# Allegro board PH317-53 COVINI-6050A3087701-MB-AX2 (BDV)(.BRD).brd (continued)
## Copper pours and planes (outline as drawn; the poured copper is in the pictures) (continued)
VCCPRIM_1P2 on TOP: 250.52,56.24 250.52,54.08 250.69,53.9 251.89,53.9 252.19,54.21 252.19,55.3 252.57,55.68 252.93,55.68 253.13,55.88 253.13,56.54 252.93,56.75 251.02,56.75
VCCSFR on TOP: 229.84,55.43 229.84,54 229.92,53.93 231.82,53.93 231.85,53.95 231.85,56.06 231.8,56.11 230.53,56.11
ACDRV on BOTTOM (solid shape): 45.34,45.77 45.34,44.5 43.3,44.5 43.18,44.63 43.18,45.9 43.3,46.03 45.08,46.03
ACDRV on BOTTOM: 37.59,46.03 38.73,46.03 39.37,46.66 40.13,46.66 40.26,46.79 40.26,48.06 40.13,48.19 39.37,48.19 38.48,47.3 37.59,47.3 37.33,47.04 37.33,46.28
FB_PLLAVDD on L5: 178.9,140.16 178.9,138.78 180.14,137.54 186.88,137.54 193.91,144.58 193.91,156.17 190.22,159.87 189.37,159.87 188.77,159.27 188.77,157.31 190.17,155.91 190.17,144.13 186.31,140.28 179.01,140.28
FB_PLLAVDD on L10: 174.19,121.47 177.63,121.47 178.74,122.59 178.74,139.33 178.45,139.62 178.05,140.02 164.38,140.02 164.15,140.25 164.15,141.6 164.77,142.22 179.23,142.22 179.43,142.42 180.29,142.42 181.16,141.54 181.16,141.18 181.63,140.71 181.63,140.07 181.68,140.01 181.68,139.59 181.81,139.47 181.81,138.74 181.62,138.55 181.62,136.71 181.51,136.61 181.08,136.18 181.08,123.52 181.18,123.42 181.66,123.42 181.78,123.31 181.78,119.56 181.14,118.93 174.24,118.93 174.01,119.15 174.01,121.29
GPPJ_RCOMP on BOTTOM: 258.65,65.11 258.65,64.68 258.9,64.42 259.36,64.42 259.97,65.03 259.97,65.48 259.71,65.74 259.28,65.74
GPU_PLLVDD_XS_SP on L3: 175.27,142.76 180.65,142.76 181.32,142.08 181.32,120.09 179.99,118.76 157.54,118.76 156.92,119.38 156.92,120.57 157.62,121.27 157.62,126.52 155.03,129.11 155.03,129.57 158.75,129.57 158.76,129.55 159.94,129.55 159.95,129.54 159.95,122.64 161.07,121.52 169.04,121.52 169.39,121.18 177.72,121.18 178.2,121.66 178.78,122.24 178.78,139.22 177.67,140.33 174.94,140.33 174.81,140.46 174.81,142.3
GPU_PLLVDD_XS_SP on L5: 175.03,140.47 185.92,140.47 189.84,144.38 189.84,155.88 189.56,156.16 188.14,156.16 185.46,153.49 185.46,148.58 180.26,143.38 175.89,143.38 175.03,142.52
LAN_LX on TOP: 280.69,98.71 280.82,98.84 281.78,98.84 281.78,98.61 281.62,98.45 281.48,98.45 280.62,97.59 280.62,96.24 280.51,96.14 279.63,96.14 279.55,96.22 279.55,98.3 279.63,98.38 280.36,98.38 280.37,98.39 280.39,98.39 280.59,98.49 280.69,98.69
Net_11604 on TOP (solid shape): outline of 162 points within 303.22,181.79 308.51,183.7
Net_11605 on BOTTOM (solid shape): outline of 162 points within 303.22,181.79 308.51,183.7
Net_11606 on TOP (solid shape): outline of 162 points within 2.99,-145.44 8.28,-143.53
Net_11607 on BOTTOM (solid shape): outline of 162 points within 2.99,-145.44 8.28,-143.53
NVHS_DVDD on TOP: 162.08,117.84 161.96,117.97 161.96,118.12 161.89,118.19 161.89,118.76 161.46,119.18 161.46,119.69 161.54,119.76 162.89,119.76 162.89,119.18 163.29,118.77 163.29,117.94 163.2,117.84
NVHS_DVDD on BOTTOM: 161.01,119.06 161.19,118.88 161.45,118.88 161.87,119.3 162.15,119.3 162.24,119.21 162.24,119.01 162.1,118.87 162.1,117.99 162.16,117.94 162.86,117.94 163,118.08 163,118.74 162.87,118.88 162.87,119.13 162.12,119.87 162.12,120.34 161.96,120.5 161.4,120.5 161.01,120.11
NVHS_HVDD on TOP: 164.3,119.18 164.3,120.18 164.82,120.71 164.82,120.76 164.85,120.78 166.33,120.78 166.41,120.7 166.41,120.29 166.41,120.29 166.41,119.53 166.06,119.18
NVHS_HVDD on BOTTOM: 164.95,118.67 164.27,119.35 163.63,119.35 163.25,119.74 163.25,119.87 163.55,120.18 163.55,120.56 163.9,120.91 166.23,120.91 166.44,120.7 166.44,119.74 165.86,119.15 165.86,119.06 165.47,118.67
PUSB3_PWR2 on TOP (solid shape): 309.62,10.14 309.62,6.28 309.09,5.74 307.16,5.74 306.96,5.95 306.96,10.16 307.11,10.32 309.44,10.32
PUSB3_PWR2 on BOTTOM (solid shape): 309.65,11.54 309.65,6.28 309.55,6.18 307.87,6.18 307.77,6.28 307.77,11.56 307.84,11.64 309.55,11.64
PUSB3_PWR2 on L5: 312.75,16.36 313,16.11 313,9.63 309.27,5.9 307.03,5.9 306.83,6.1 306.83,15.85 307.34,16.36
PV_RGLI on TOP: 295.3,80.65 295.3,77.55 292.43,77.55 292.12,77.85 291.46,77.85 291.44,77.83 291.18,77.83 291.18,77.96 291.59,78.36 294.38,78.36 294.51,78.49 294.51,80.65
PV_RGLRO on TOP: 294.13,78.62 291.61,78.62 291.03,78.03 290.8,78.03 290.8,79.23 291.03,79.45 294.13,79.45 294.15,79.43 294.15,78.64
PVADPTR on TOP: 29.59,66.22 30.95,64.86 30.95,63.82 32.18,62.59 32.18,50.85 33.19,49.84 42.97,49.84 43.48,50.35 43.48,53.83 44.62,54.97 44.62,60.2 48.05,63.63 48.05,67.31 40.13,75.24 24.53,75.24 21.94,77.83 21.94,81.69 21.51,82.12 8.38,82.12 7.82,81.56 7.82,70.34 11.93,66.22
PVADPTR on BOTTOM: 13.71,81.84 13.87,81.99 16.18,81.99 16.33,81.84 16.33,78.11 16,77.78 14.14,77.78 13.71,78.21
PVADPTR on BOTTOM: 45.34,54.16 45.72,53.78 45.72,50.22 44.07,48.57 38.6,48.57 38.33,48.84 38.33,49.48 36.4,51.42 36.4,53.74 36.81,54.16
PVCORE on TOP (solid shape): 118.49,129.16 115.67,129.16 115.67,130 115.72,130.05 118.49,130.05
PVCORE on TOP (solid shape): 108.1,130.31 108.1,129.16 106.04,129.16 106.04,130.38 106.24,130.58 107.82,130.58
PVCORE on TOP (solid shape): 114.04,139.37 114.04,138.71 112.06,138.71 112.06,139.53 112.09,139.55 113.86,139.55
PVCORE on TOP (solid shape): 104.26,130.81 104.21,130.76 104.21,128.4 104.04,128.22 103.7,128.22 103.4,128.53 103.4,130.99 104.09,130.99
PVCORE on TOP (solid shape): 110.23,137.14 110.23,135.44 110.21,135.41 109.6,135.41 109.5,135.51 109.5,137.19 109.65,137.34 110.03,137.34
PVCORE on TOP (solid shape): 112.8,136.78 112.8,136.33 112.95,136.17 112.95,135.69 112.16,135.69 112.06,135.79 112.06,136.91 112.67,136.91
PVCORE on TOP (solid shape): 112.85,130.41 112.85,129.21 112.8,129.16 110.92,129.16 110.82,129.26 110.82,129.75 111.66,130.58 112.67,130.58
PVCORE on TOP (solid shape): 106.58,134.75 106.24,134.42 106.24,130.99 105.1,130.99 105.05,131.04 105.05,134.57 105.2,134.73 105.69,134.73 105.69,137.06 106.58,137.06
PVCORE on TOP (solid shape): 109.09,139.5 109.09,139.04 108.84,138.79 104.44,138.79 104.42,138.81 104.42,139.25 104.85,139.68 108.91,139.68
PVCORE on TOP (solid shape): 117.6,136.81 117.6,130.51 117.04,130.51 116.81,130.74 116.81,136.66 117.01,136.86 117.55,136.86
PVCORE on TOP (solid shape): 115.44,136.81 115.44,134.62 115.77,134.29 115.77,133.73 115.97,133.53 116.1,133.53 116.13,133.51 116.13,133.05 115.26,133.05 115.26,133.79 114.5,134.55 114.5,136.88 115.36,136.88
PVCORE on TOP: 113.98,125.37 113.74,125.61 113.74,126.06 113.59,126.2 112.3,126.2 112.25,126.15 112.25,125.91 112.02,125.68 111.33,125.68 111.14,125.68 110.98,125.53 102.15,125.53 101.44,126.24 101.44,126.96 103.1,128.62 103.17,128.55 103.37,128.55 103.4,128.58 103.88,128.58 104.01,128.71 104.01,130.25 103.91,130.36 103.27,130.36 103.18,130.45 103.18,136.34 103.84,137 103.84,137.68 103.88,137.72 103.88,138.87 103.63,139.12 102.36,139.12 102.36,139.14 102.13,139.37 102.13,147.98 100.45,149.66 100.45,156.52 101.22,157.28 101.24,157.28 101.24,158.4 101.39,158.55 102.64,158.55 102.87,158.32 102.87,157.69 103.27,157.28 113.99,157.28 113.99,153.98 113.92,153.9 112.39,153.9 111.91,153.42 111.91,150.17 112.11,149.97 112.44,149.97 112.8,149.61 117.55,149.61 117.83,149.89 117.83,153.67 117.62,153.88 116.66,153.88 116.63,153.9 116.63,158.42 116.66,158.45 117.65,158.45 118.82,157.28 130.07,157.28 130.6,156.75 130.6,145.22 130.43,145.04 119.59,145.04 119.59,144.46 119.08,143.95 119.08,138.04 119.11,138.02 119.11,138.02 119.96,137.17 119.96,127.08 120.34,126.7 120.34,125.5 120.22,125.37 ; 13 cut-outs
PVCORE on BOTTOM: 120.27,136.52 120.21,136.7 120.2,136.72 120.15,136.82 120.13,136.93 119.87,137.2 119.16,137.2 119.07,137.28 119.07,145.49 119.79,144.78 131.64,144.78 131.96,145.1 131.96,151.96 132.64,152.63 132.64,157.61 132.43,157.81 126.15,157.81 126.23,157.89 97.58,157.89 97.57,157.88 96.73,157.88 96.14,157.28 96.14,153.98 96.9,153.98 100.25,150.63 100.25,149.74 101.38,148.61 101.38,147.1 101.94,146.54 101.94,143.65 102.12,143.33 101.94,143.02 101.94,142.35 102.08,142.21 102.12,142.02 102.14,141.98 102.17,141.97 102.29,141.94 102.37,141.86 102.37,141.85 102.49,141.74 102.52,141.74 102.91,141.38 102.52,141.03 102.49,141.03 102.32,140.86 102.26,140.83 102.21,140.81 102.17,140.8 102.15,140.78 102.15,140.77 101.98,140.6 101.98,137.66 102.13,137.51 102.76,137.51 103.13,137.14 119.65,137.14
PVCORE on BOTTOM: 102.05,125.22 101.4,125.88 101.4,128.23 102.39,129.23 119.07,129.23 119.07,127.64 119.45,127.26 120.01,127.26 120.06,127.21 120.65,127.21 120.92,126.94 120.92,126.46 120.93,126.44 121.52,126.44 121.87,126.09 121.87,125.32 121.85,125.3 120.29,125.3 120.29,125.22
PVCORE on L3: 101.27,125.31 101.09,125.49 101.09,134.57 101.98,135.47 101.98,146.28 100.73,147.53 100.73,152.99 101.22,153.47 110.66,153.47 110.66,149.33 111.07,148.92 111.12,148.92 111.35,149.15 118.72,149.15 118.87,149 118.87,138.05 120.34,136.58 120.34,127.08 120.34,127.08 120.33,126.13 119.53,125.33 110.82,125.33 110.8,125.35 110.76,125.31
PVCORE on L5: 113.98,125.37 113.74,125.61 113.74,126.06 113.59,126.2 112.3,126.2 112.25,126.15 112.25,125.91 112.02,125.68 111.33,125.68 111.14,125.68 110.98,125.53 101.09,125.53 100.99,125.63 100.99,153.52 101.22,153.75 111.55,153.75 111.81,153.5 111.81,150.07 112.37,149.51 117.73,149.51 118.01,149.79 118.01,153.62 118.13,153.75 130.37,153.75 130.6,153.52 130.6,145.22 130.43,145.04 119.59,145.04 119.59,144.46 119.08,143.95 119.08,138.04 119.11,138.02 119.11,138.02 119.96,137.17 119.96,127.08 120.34,126.7 120.34,125.5 120.22,125.37 ; 1 cut-out
PVCORE on L6: 101.6,160.2 130.68,160.2 130.68,144.96 119.45,144.96 119.36,140.32 119.36,140.32 119.38,137.29 119.6,137.09 120.27,137.09 120.27,125.53 101.6,125.53 101.6,147.37 101.09,147.88 101.09,159.82 101.34,159.82 101.6,160.07
PVCORE on L8: 101.98,136.55 101.98,146.28 100.73,147.53 100.73,152.53 100.96,152.76 111.15,152.76 111.48,152.43 111.48,150.17 112.14,149.51 117.62,149.51 117.9,149.79 117.9,153.55 118.11,153.75 130.37,153.75 130.65,153.47 130.65,145.27 130.4,145.01 120.28,145.01 120.03,144.76 120.03,137.56 119.02,136.55
PVCORE on L10: 119.99,127.36 114.5,127.36 113.66,126.52 112.52,126.52 112.19,126.85 107.74,126.85 107.72,126.83 103.25,126.83 101.09,128.98 101.09,134.57 101.98,135.47 101.98,146.86 100.96,147.88 100.96,152.78 117.95,152.78 117.95,153.65 126.36,153.65 126.36,153.62 130.04,153.62 130.71,152.96 130.71,145.16 130.4,144.86 128.7,144.86 128.55,145.01 119.78,145.01 119.13,144.36 119.13,137.56 120.16,136.53 120.16,127.54 ; 1 cut-out
PVCORE_DGPU on TOP (solid shape): 204.92,80.01 204.92,78.03 205.27,77.69 207.07,77.69 207.36,77.4 207.36,75.49 207.16,75.29 195.12,75.29 194.94,75.47 194.94,79.58 195.53,80.17 204.77,80.17
PVCORE_DGPU on TOP (solid shape): 184.5,79.05 184.5,75.52 184.27,75.29 169.21,75.29 169.01,75.49 169.01,76.64 169.16,76.79 172.44,76.79 172.62,76.79 175.76,79.94 183.61,79.94
PVCORE_DGPU on TOP: outline of 176 points within 145.28,121.9 177.96,152.43 ; 4 cut-outs
PVCORE_DGPU on BOTTOM: 159.74,71.25 160.45,71.96 162.91,71.96 165.53,74.58 165.53,76.05 166.32,76.84 172.67,76.84 175,79.18 175,79.99 175.13,80.12 184.1,80.12 184.5,79.71 184.5,72.06 184.76,71.81 194.1,71.81 195.02,72.72 195.02,83.09 196.69,84.76 196.69,88.7 196.97,88.98 198.02,88.98 198.12,88.88 198.12,81.36 199.26,80.22 204.72,80.22 205.2,79.73 205.2,78.11 205.46,77.85 207.13,77.85 207.59,77.4 207.59,76.1 208.1,75.59 213.31,75.59 213.81,75.09 213.81,66.15 213.64,65.97 213.64,65.94 159.99,65.94 159.74,66.2
PVCORE_DGPU on BOTTOM: 160.63,143.37 160.63,143.07 160.79,142.91 161.11,142.91 161.22,143.01 161.46,143.01 161.47,143 161.47,142.78 161.6,142.65 161.87,142.65 162.25,142.27 162.25,142.11 162.84,141.52 162.84,141.14 163.57,140.41 178.69,140.41 178.97,140.13 178.97,129.11 178.95,128.99 178.97,128.87 178.97,121.16 178.81,121 159.7,121 159.57,121.13 159.57,122.14 159.25,122.47 159.25,122.56 159.31,122.56 159.31,123.17 159.25,123.17 159.25,128.91 159.31,128.91 159.31,129.7 159.25,129.7 159.25,137.04 156.77,139.52 156.77,140.17 154.79,142.14 154.79,142.33 154.44,142.68 153.51,142.68 153.18,143.01 153.18,143.49 152.57,144.1 151.71,144.1 151.29,144.52 150.73,144.52 149.92,145.33 148.32,145.33 147.47,146.18 147.24,146.18 147.09,146.33 147.09,149.08 146.76,149.41 144.98,149.41 144.88,149.51 144.88,152.71 146.38,154.21 155.98,154.21 156.41,154.64 157.38,154.64 157.76,154.26 157.76,152.1 157.58,151.92 156.97,151.92 156.23,151.18 156.23,148.8 157.34,147.69 157.34,147.09 158.55,145.88 159.41,145.02 159.41,144.52 159.85,144.08 159.85,143.84 160.05,143.64 160.41,143.64 160.52,143.75 160.66,143.75 160.73,143.68 160.73,143.47 ; 22 cut-outs
PVCORE_DGPU on L3: 169.61,121.36 169.31,121.66 161.28,121.66 161.04,121.89 160.97,121.89 160.04,122.83 160.04,136.68 158.88,137.84 153.72,143.01 147.42,143.01 146.45,143.97 146.45,154.11 146.73,154.38 155.72,154.38 156.08,154.03 156.08,148.52 159.26,145.34 160.45,145.34 163.38,142.41 174.23,142.41 174.39,142.25 174.39,140.47 174.81,140.05 177.75,140.05 178.68,139.12 178.68,122.37 177.66,121.36
PVCORE_DGPU on L5: 155.85,72.57 150.36,78.06 150.36,85.91 149.73,86.54 147.01,86.54 145.64,87.91 145.64,95.05 145.39,95.3 145.39,109.38 146.38,110.37 146.38,120.17 145.16,121.39 145.16,125.56 145.51,125.91 145.51,138.99 147.88,141.35 147.88,148.24 153.69,154.05 173.68,154.05 174.44,153.29 174.44,141.07 175.3,140.21 175.71,140.21 175.71,140.2 178.51,140.2 178.65,140.06 178.65,138.8 180.24,137.21 194.31,137.21 195.07,136.45 195.07,99.77 200.4,94.44 200.4,90 208.45,81.94 208.45,72.85 208.2,72.6 206.8,72.6 206.8,72.57 ; 1 cut-out
PVCORE_DGPU on L6: 146.05,137.09 146.05,69.02 153.29,69.02 156.71,65.59 208.4,65.59 208.4,85.02 200.53,85.02 194.94,90.61 194.94,150.22 156.13,150.22 156.13,151.79 151.13,151.79 151.13,142.17 ; 1 cut-out
PVCORE_DGPU on L8: 161.87,141.82 161.35,141.82 158.42,144.76 158.42,145.29 158.13,145.57 157.6,145.57 155.65,147.52 155.65,148.27 155.11,148.82 155.11,149.36 154.38,150.09 154.38,152.28 154.1,152.56 152.02,152.56 149.78,150.32 149.78,147.09 159.85,137.02 159.85,126 160.6,125.25 160.6,121.41 160.7,121.31 177.67,121.31 178.69,122.33 178.69,139.2 177.91,139.98 163.71,139.98 162.54,141.15
PVCORE_DGPU on L10: 169.9,121.54 169.76,121.68 161.18,121.68 160.76,122.11 160.04,122.82 160.04,134.23 159.74,134.53 159.74,137.44 157.91,139.27 157.91,139.32 156.51,140.72 156.51,146.23 156.59,146.31 157.45,146.31 163.78,139.98 163.95,139.81 177.96,139.81 178.64,139.13 178.64,122.88 177.31,121.54
PVPACK on TOP: 17.27,34.22 18.79,34.22 19.05,33.96 19.05,32.06 18.79,31.8 17.4,31.8 17.14,32.06 17.14,34.09
PVPACK on BOTTOM: 17.4,34.73 20.57,34.73 20.82,34.47 20.82,32.16 22.07,30.92 32.76,30.92 33.75,31.91 33.75,32.67 33.91,32.82 38.48,32.82 38.6,32.69 38.6,29.9 38.22,29.52 35.3,29.52 32.36,26.57 17.85,26.57 17.14,27.28 17.14,34.47
PWR_DP on BOTTOM (solid shape): 300.52,38.51 300.52,36.2 300.5,36.18 300.5,36.1 300.27,35.86 297.03,35.86 296.89,36.01 296.89,38.51 297.14,38.76 300.27,38.76
SPK_OUT_L_N on TOP: 24.08,57.18 24.08,57.48 24.69,58.09 25.73,58.09 25.85,57.97 25.85,57.26 25.73,57.13 24.13,57.13
SPK_OUT_L_P on TOP: 24.33,56.06 25.88,56.06 25.88,56.77 25.75,56.9 24.33,56.9 24.13,56.7 24.13,56.26
SPK_OUT_R_L_N on TOP: 26.77,57.2 26.64,57.33 26.64,57.94 26.72,58.02 27.53,58.02 27.84,58.32 28.75,58.32 28.85,58.22 28.85,57.84 28.67,57.66 28.19,57.66 27.73,57.2
SPK_OUT_R_L_P on TOP: 26.72,56.16 28.27,56.16 28.93,56.82 29.33,56.82 29.44,56.92 29.44,57.51 29.38,57.56 28.93,57.56 28.75,57.38 28.27,57.38 27.71,56.82 26.82,56.82 26.72,56.72
SPK_OUT_R_N on TOP: 25.88,58.37 24.74,58.37 24.61,58.25 24.2,58.25 24.19,58.26 24.19,58.54 24.18,58.55 24.18,59.01 24.41,59.24 25.75,59.24 25.9,59.08 25.9,58.4
SPK_OUT_R_P on TOP: 25.9,59.52 24.2,59.52 24.18,59.54 24.18,60.18 24.3,60.3 25.78,60.3 25.9,60.18
SPK_OUT_R_R_N on TOP: 26.62,59.13 26.62,58.4 27.56,58.4 27.75,58.59 28.65,58.59 28.72,58.66 28.72,59.19 28.67,59.24 26.72,59.24
SPK_OUT_R_R_P on TOP: 26.64,60.23 26.64,59.57 26.72,59.49 28.7,59.49 28.8,59.59 28.8,60.3 28.72,60.38 26.79,60.38
UNNAMED_129_BEADSINGLE_I11_INB on BOTTOM: 3.04,80.83 3.04,76.13 3.55,75.62 10.56,75.62 10.84,75.34 10.84,74.17 10.94,74.07 12.44,74.07 12.75,74.37 12.75,76.56 13.01,76.83 13.01,81.21 12.76,81.46 11.81,81.46 11.55,81.21 3.43,81.21
UNNAMED_130_CAPALSP_I76_A on BOTTOM (solid shape): 52.5,33.96 54.33,33.96 54.61,33.68 54.61,30.41 54.45,30.25 52.22,30.25 52.17,30.31 52.17,31.17 51.61,31.73 44.57,31.73 44.47,31.83 44.47,32.77 44.98,33.28 44.98,34.29 45.16,34.47 51.99,34.47
UNNAMED_130_CSC0603_I106_A on BOTTOM: 43.91,33.18 43.81,33.28 40.61,33.28 40.41,33.07 40.41,31.68 39.93,31.19 39.93,29.72 39.6,29.39 39.14,29.39 37.94,28.2 36.62,28.2 36.5,28.07 36.5,25.05 36.65,24.9 43.79,24.9 43.91,25.02
UNNAMED_142_CSC0603_I5_A on BOTTOM (solid shape): 83.44,147.07 83.44,145.8 82.85,145.22 82.39,145.22 81.96,145.65 81.94,145.65 81.23,146.36 81.23,146.66 81.38,146.82 81.38,147.02 81.23,147.17 81.23,147.2 81.66,147.63 81.76,147.63 82.01,147.37 82.37,147.37 82.7,147.7 82.8,147.7
UNNAMED_155_CN102G_I26_1 on BOTTOM (solid shape): 267.13,31.42 267.51,31.42 267.93,31 267.99,30.9 267.99,30.05 266.74,28.8 266.68,28.77 266.61,28.79 266.56,28.83 266.49,28.85 266.1,28.85 265.99,28.81 265.92,28.73 265.91,28.71 261.41,28.71 261.18,28.93 261.18,31.27 261.46,31.55 267,31.55
UNNAMED_160_APCI0020P003A_I103_ on BOTTOM: 64.51,34.65 64.51,52.05 64.84,52.38 64.84,53.6 65.35,54.11 69.21,54.11 69.44,53.88 69.44,52.18 68.04,52.18 66.93,51.06 66.93,39.78 67.28,39.42 69.92,39.42 70.18,39.17 70.18,35.11 69.8,34.73 69.3,34.65
UNNAMED_161_APCI0020P003A_I118_ on BOTTOM: 175.1,23.85 175.23,23.98 182.5,23.98 184.32,25.81 184.32,29.29 176.98,36.63 174.55,36.63 174.42,36.76 174.42,40.87 174.55,41 181.1,41 181.23,40.87 181.23,38.94 181.89,38.28 183.38,38.28 183.51,38.15 183.51,37.77 182.98,37.24 182.98,35.89 187.5,31.37 187.5,23.6 185.9,22 181.02,22 180.9,21.87 180.9,21.97 180.77,21.85 175.23,21.85 175.1,21.97
UNNAMED_166_CN405G_I84_34 on BOTTOM (solid shape): 29.08,64.37 29.36,64.09 29.36,62.77 29.23,62.64 28.62,62.64 28.39,62.87 28.39,64.27 28.55,64.42 29.08,64.42
UNNAMED_166_CN405G_I84_34 on BOTTOM: 27.35,64.7 27.76,65.1 28.14,65.1 28.32,65.28 28.32,66.65 28.42,66.75 28.98,66.75 29.08,66.65 29.08,64.37 29.26,64.19 29.26,62.69 29.16,62.59 27.56,62.59 27.35,62.79
UNNAMED_166_CN405G_I84_39 on TOP: 25.17,65.92 25.17,65.13 25.07,65.03 23.47,65.03 23.36,65.13 23.36,65.89 23.47,65.99 25.09,65.99
UNNAMED_166_CN405G_I84_39 on BOTTOM: 26.54,65.26 26.36,65.08 20.62,65.08 20.37,65.33 20.37,68.61 20.62,68.86 20.62,70.03 22.12,71.53 25.5,71.53 25.47,71.5 25.47,69.24 25.57,69.14 26.41,69.14 26.54,69.02
UNNAMED_166_FUSE_I171_1 on BOTTOM (solid shape): 48.59,85.37 48.59,80.01 48.43,79.86 47.82,79.86 47.55,80.14 47.55,80.34 47.47,80.42 47.36,80.42 47.35,80.43 46.8,80.43 46.8,80.42 46.66,80.42 46.45,80.62 46.45,85.3 46.68,85.53 48.43,85.53
UNNAMED_166_NCT3521U_I118_OUT on BOTTOM: 18.67,79.43 18.67,77.73 18.72,77.68 19.61,77.68 20.11,78.18 20.75,78.18 20.85,78.08 20.85,77.93 21.13,77.65 22.15,77.65 22.35,77.85 22.35,79.58 22.22,79.71 18.95,79.71
UNNAMED_259_CSC0402_I133_A on BOTTOM: 288.85,101.43 290.42,101.43 290.52,101.32 290.52,99.47 290.34,99.29 288.92,99.29 288.72,99.09 288.72,97.46 288.46,97.21 287.65,97.21 287.4,97.46 287.4,97.52 287.43,97.59 287.52,97.61 287.55,97.6 287.85,97.6 287.99,97.67 288.05,97.8 288.05,98.2 288.02,98.29 287.94,98.37 287.9,98.44 287.95,98.52 288.02,98.59 288.05,98.69 288.05,99.08 287.99,99.22 287.85,99.29 287.75,99.29 287.68,99.33 287.67,99.41 287.63,99.67 287.43,99.83 287.4,99.85 287.4,100.27 287.42,100.33 287.48,100.36 287.81,100.71 287.48,101.07 287.42,101.1 287.4,101.16 287.4,101.78 287.44,101.79 287.72,102.07 287.55,102.44 287.51,102.51 287.53,102.58 287.62,102.9 287.4,103.15 287.39,103.16 287.07,103.48 287.07,106.53 287.4,106.86 287.41,106.88 288.05,107.71 288.4,108.69 288.4,108.7 288.79,109.1 290.32,109.1 290.52,108.89 290.52,107.04 290.39,106.91 288.95,106.91 288.74,106.71 288.74,104.64 288.71,104.57 288.64,104.55 288.25,104.19 288.64,103.84 288.71,103.82 288.74,103.75 288.74,101.53
UNNAMED_265_APL3523A_I456_8 on BOTTOM: 227.96,33.48 228.04,33.56 228.04,35.21 227.96,35.28 225.8,35.28 225.8,35.69 225.78,35.72 225.55,35.72 225.37,35.89 224.53,35.89 224.41,35.77 224.41,33.61 224.53,33.48
UNNAMED_265_APL3523A_I456_13 on BOTTOM (solid shape): 232.91,35.28 232.91,34.22 232.64,33.94 232.41,33.94 232.41,33.77 232.4,33.77 232.4,32.74 232.38,32.72 231.7,32.72 230.86,33.56 229.46,33.56 229.37,33.64 229.37,34.02 229.36,34.09 229.33,34.16 229.33,34.93 229.87,35.46 232.74,35.46
UNNAMED_265_APL3523A_I457_13 on BOTTOM (solid shape): 278.43,61.7 278.43,59.57 278.23,59.36 277.49,59.36 276.98,59.87 276.64,59.87 276.64,59.88 275.61,59.88 275.54,59.95 275.54,61.47 275.84,61.78 278.36,61.78
UNNAMED_319_CSC0402_I39_A on BOTTOM (solid shape): 151.66,165.1 151.66,162.77 151.53,162.64 146.66,162.64 146.38,162.92 145.97,162.92 145.97,163.02 145.72,163.27 145.72,163.35 145.56,163.5 145.55,163.52 145.11,163.52 145.11,164.01 145.21,164.11 145.74,164.11 145.87,164.24 145.87,165.23 145.97,165.33 151.43,165.33
UNNAMED_319_CSC0603_I29_A on BOTTOM (solid shape): 154.5,169.67 154.76,169.67 155.07,169.36 155.09,169.3 155.11,169.26 155.11,166.07 154.86,165.81 154.67,165.81 154.67,165.82 154.22,165.82 154.14,165.9 154.02,166.1 154.02,166.35 153.92,166.45 153.41,166.45 153.41,166.7 153.72,167.01 153.72,168.38 153.31,168.79 153.31,169.68 154.48,169.68
UNNAMED_403_APL3537BHAI_I10_A1 on BOTTOM: 159.79,88.83 159.79,88.07 159.89,87.96 160.75,87.96 160.79,88 160.84,88 161.03,88.19 161.03,88.98 160.98,89.03 159.99,89.03
UNNAMED_410_NMOSC_I395_D on BOTTOM (solid shape): 208.02,177.78 208.02,176.23 207.72,175.92 202.76,175.92 201.8,176.89 201.8,177.78 201.88,177.85 207.95,177.85
UNNAMED_410_NMOSC_I397_D on TOP (solid shape): 213.89,171.5 213.89,170.06 213.76,169.93 205.79,169.93 205.74,169.98 205.74,171.58 205.81,171.66 213.74,171.66
UNNAMED_410_NMOSC_I444_D on BOTTOM (solid shape): 201.04,88.9 201.04,84.74 200.94,84.64 200.12,84.64 200.02,84.53 200.02,83.01 199.77,82.76 198.9,82.76 198.8,82.86 198.8,88.75 199.06,89.01 200.94,89.01
USB_CHR_POWER on TOP (solid shape): 300.35,33.18 301.24,33.18 301.24,32.87 301.22,32.85 299.67,32.85 299.62,32.79 297.53,32.79 297.46,32.87 297.46,33.33 297.51,33.38 300.15,33.38
USB_CHR_POWER on TOP: 286.46,32.26 287.42,32.26 287.55,32.13 287.91,32.13 288.49,31.55 294.8,31.55 297.59,31.56 298.07,32.03 298.07,33.38 297.25,33.38 296.52,32.64 295.68,32.64 295.17,32.13 290.75,32.13 290.65,32.24 290.65,32.54 289.96,33.23 288.74,33.23 288.46,32.95 286.46,32.95 286.33,32.82 286.33,32.39
USB_CHR_POWER on TOP: 301.11,25.05 302.66,26.6 305.08,26.6 306.12,27.64 306.12,29.49 305.74,29.87 302.21,29.87 301.69,29.35 301.69,28.01 301.16,27.49 299.79,27.49 297.89,25.58 297.89,21.24 298.14,20.98 300.3,20.98 301.11,21.8
USB_CHR_POWER on BOTTOM: 305.89,28.38 306.22,28.71 306.22,29.72 304.31,31.63 301.6,31.63 301.52,31.55 301.52,28.86 302,28.38
USB_CHR_POWER on L10: 289.56,34.24 302.49,34.24 303.17,33.56 303.17,31.25 303.67,30.75 305.98,30.75 306.19,30.53 306.19,28.68 305.97,28.45 301.65,28.45 299.11,30.99 289.53,30.99 289.28,31.25 289.28,33.96
VADPBL on BOTTOM (solid shape): 44.73,48.19 44.81,48.14 44.82,48.05 44.8,48.01 44.79,47.97 44.79,47.58 44.86,47.44 45,47.37 45.27,47.37 45.34,47.37 45.34,46.54 45.08,46.28 42.8,46.28 42.67,46.16 42.67,44.63 38.22,44.63 37.97,44.89 37.97,45.77 38.99,45.77 39.62,46.41 40.51,46.41 40.76,46.66 40.76,48.06 40.89,48.19
VRA_SY8284_VCC on TOP (solid shape): 199.29,174.68 199.84,174.68 199.89,174.63 199.89,174.27 199.84,174.22 198.4,174.22 198.17,174.45 198.17,174.98 198.24,175.06 198.9,175.06
VRACHG_MP1 on BOTTOM: 39.24,44.25 45.97,44.25 46.22,44.5 46.22,45.01 46.35,45.14 46.86,45.14 46.99,45.01 46.99,40.57 46.61,40.19 45.06,40.19 43.91,39.04 39.37,39.04 38.99,39.42 38.99,44
VRACPU_PH1 on BOTTOM (solid shape): 97.28,169.85 97.28,168.71 97.53,168.46 101.6,168.46 101.85,168.2 101.85,163.25 101.72,163.12 99.9,163.12 99.9,166.54 100,166.54 100,167.17 99.28,167.17 99.28,166.54 99.39,166.54 99.39,163.12 97.25,163.12 94.87,165.51 94.87,169.6 95.25,169.98 97.15,169.98
VRACPU_PH2 on BOTTOM (solid shape): 107.64,169.86 107.64,168.71 107.9,168.46 111.96,168.46 112.22,168.2 112.22,163.25 112.09,163.12 110.26,163.12 110.26,166.51 110.36,166.51 110.36,167.15 109.65,167.15 109.65,166.51 109.75,166.51 109.75,163.12 106.37,163.12 106.3,163.2 106.3,166.45 106.3,169.73 106.55,169.98 107.52,169.98
VRACPU_PH3 on BOTTOM (solid shape): 118.06,169.85 118.06,168.71 118.31,168.46 122.38,168.46 122.63,168.2 122.63,163.25 122.51,163.12 120.67,163.12 120.67,166.51 120.77,166.51 120.77,167.15 120.06,167.15 120.06,166.51 120.16,166.51 120.16,163.12 116.79,163.12 116.71,163.2 116.71,169.72 116.97,169.98 117.93,169.98
VRACPU_PH4 on BOTTOM (solid shape): 128.42,169.9 128.42,168.76 128.68,168.5 128.83,168.5 132.74,168.5 133,168.25 133,163.3 132.87,163.17 131.06,163.17 131.06,166.51 131.16,166.51 131.16,167.15 130.45,167.15 130.45,166.51 130.55,166.51 130.55,163.17 127.15,163.17 127.08,163.25 127.08,169.77 127.33,170.03 128.3,170.03
VRAM_DGPU_PH1 on BOTTOM (solid shape): 221.31,76.53 221.31,73.82 220.95,73.46 220.95,68.84 220.82,68.71 218.79,68.71 218.67,68.84 218.67,73.21 218.34,73.54 217.14,73.54 216.86,73.82 216.86,73.91 219.89,73.91 219.89,74.55 219.18,74.55 219.18,73.91 216.86,73.91 216.86,76.48 217.17,76.79 221.05,76.79
VRAM_DGPU_PH2 on BOTTOM (solid shape): 232.99,76.08 232.99,73.82 232.81,73.64 230.91,73.64 230.7,73.43 230.7,68.79 230.58,68.66 228.37,68.66 228.24,68.79 228.24,73.93 231.6,73.93 231.6,74.56 230.89,74.56 230.89,73.93 228.24,73.93 228.24,76.13 228.55,76.43 232.64,76.43
VRAP1V0S_DGPU_FB on BOTTOM (solid shape): 154.07,172.29 154.07,170.84 153.31,170.84 153.31,172.32 154.05,172.32
VRAVDDQ_BST on BOTTOM (solid shape): 70.89,80.7 70.63,80.45 69.62,80.45 69.19,80.01 68.78,80.01 68.78,80.93 68.83,80.98 70.33,80.98 70.43,81.08 70.43,81.66 70.46,81.69 70.89,81.69
VRB5V0A_BST on TOP (solid shape): 246.73,28.15 246.73,26.39 245.82,25.48 245.69,25.48 245.69,27.16 245.92,27.38 245.92,28.16 245.93,28.17 246.71,28.17
VRB5V0A_VCC on TOP (solid shape): 247.04,23.73 247.04,22.86 246.81,22.63 246.2,22.63 246.07,22.77 246.07,23.02 246.04,23.14 245.97,23.23 245.97,23.52 245.97,23.93 246.83,23.93
VRP1V0S_DGPU_PH on BOTTOM (solid shape): 151.1,170.06 151.1,168.33 151.15,168.28 151.56,168.28 151.69,168.15 151.69,166.53 151.63,166.48 147.77,166.48 147.65,166.6 147.65,170.06 147.77,170.18 150.97,170.18
VRP1V2_PH on TOP (solid shape): 201.39,178.72 201.39,176.15 201.27,176.03 199.23,176.03 198.88,175.67 198.07,175.67 198.07,176.21 198.41,176.43 198.54,176.81 198.55,176.81 198.55,178.46 198.72,178.64 199.04,178.64 199.21,178.82 201.29,178.82
VRP1V05A on BOTTOM (solid shape): 231.14,59.97 231.14,53.57 231.14,53.03 230.83,53.03 230.83,52.94 230.35,52.94 230.21,52.8 229.35,52.8 229.25,52.71 228.06,52.71 227.99,52.78 227.99,53.55 229.79,53.55 229.79,53.49 229.8,53.44 229.81,53.39 229.84,53.34 229.87,53.3 229.9,53.26 229.95,53.23 229.99,53.2 230.04,53.18 230.09,53.17 230.15,53.16 230.2,53.17 230.25,53.18 230.3,53.2 230.35,53.23 230.39,53.26 230.42,53.3 230.45,53.34 230.48,53.39 230.49,53.44 230.5,53.49 230.5,53.55 230.49,53.6 230.48,53.65 230.45,53.7 230.42,53.74 230.39,53.78 230.35,53.82 230.3,53.84 230.25,53.86 230.2,53.87 230.15,53.88 230.09,53.87 230.04,53.86 229.99,53.84 229.95,53.82 229.9,53.78 229.87,53.74 229.84,53.7 229.81,53.65 229.8,53.6 229.79,53.55 227.99,53.55 227.99,56.87 229.77,56.87 229.77,57.58 229.14,57.58 229.14,56.87 227.99,56.87 227.99,59.95 228.11,60.07 231.04,60.07
VRP1V05A_PH on BOTTOM (solid shape): 224.53,59.08 224.53,53.01 223.97,53.01 223.94,53.01 223.87,53 223.8,52.98 223.73,52.96 223.67,52.93 223.61,52.9 223.56,52.86 223.51,52.81 223.46,52.76 223.43,52.7 223.39,52.64 223.38,52.61 222.83,52.61 222.83,53.65 222.84,53.68 222.86,53.72 222.87,53.77 222.88,53.83 222.87,53.85 222.88,53.86 222.88,54.56 222.65,54.79 222.35,54.79 222.3,54.84 222.3,56.87 223.18,56.87 223.18,57.58 222.54,57.58 222.54,56.87 222.3,56.87 222.3,59.06 222.53,59.29 224.33,59.29
VRP1V05A_VIN on BOTTOM (solid shape): 224.87,51.56 226.02,51.56 226.07,51.57 226.77,51.57 226.92,51.41 226.92,45.6 226.51,45.19 225.78,45.19 225.22,45.75 224.13,45.75 224.13,49.61 223.9,49.84 223.9,50.27 223.59,50.57 223.59,52.05 224.38,52.05
VRP1V8 on TOP: 204.24,172.65 204.31,172.57 206.47,172.57 206.78,172.88 206.78,173.82 206.96,173.99 206.96,175.54 207.51,176.1 207.51,179.61 207.39,179.73 204.39,179.73 204.24,179.58
VRP1V8A on TOP: 221.81,28.38 221.71,28.48 219.99,28.48 219.88,28.38 219.88,28.22 220.39,27.71 220.39,20.55 220.52,20.43 221.03,20.43 221.13,20.53 221.13,20.78 221.81,21.47
VRP1V8A_PH on TOP (solid shape): 219.02,25.05 219.02,21.21 218.84,21.03 217.6,21.03 217.45,21.19 217.45,22.66 217.14,22.97 216.38,22.97 216.25,23.09 216.25,23.83 216.26,23.84 216.29,23.99 216.26,24.15 216.25,24.16 216.25,24.79 216.73,25.28 218.79,25.28
VRP1V8A_VIN on TOP (solid shape): 214.78,26.44 214.78,23.24 214.63,23.09 213.76,23.09 213.28,23.57 213.28,24.11 212.95,24.44 212.95,25.53 213.46,26.04 213.67,26.04 213.67,26.04 213.92,26.04 214.42,26.55 214.68,26.55
VRP1V8S_VIN on TOP (solid shape): 195.39,179.72 197.06,179.72 197.28,179.51 197.28,177.57 197.58,177.27 197.58,176.53 196.06,176.53 195.98,176.61 195.98,177.24 195.88,177.35 195.04,177.35 194.59,176.89 194.08,176.89 193.8,176.61 189.99,176.61 189.61,176.99 189.61,178.06 189.07,178.59 189.07,179.45 189.35,179.73 195.38,179.73
VRP2V5 on BOTTOM (solid shape): 80.54,67.82 80.67,67.69 80.67,65.48 80.62,65.43 80.62,64.85 80.57,64.8 76.1,64.8 75.94,64.95 75.94,66.25 75.56,66.63 75.56,67.72 75.66,67.82 77.95,67.82
VRP2V5_PH on BOTTOM (solid shape): 80.26,63.45 80.26,60.76 80.2,60.7 80.02,60.7 80.01,60.68 78.66,60.68 78.61,60.73 78.61,62 78.38,62.23 75.94,62.23 75.89,62.28 75.89,63.53 75.94,63.58 80.13,63.58
VRP2V5_VIN on BOTTOM (solid shape): 80.84,58.78 80.84,56.98 80.72,56.85 79.09,56.85 78.84,56.59 78.46,56.59 78.36,56.7 78.36,57.36 78.64,57.64 78.64,58.78 78.76,58.91 80.72,58.91
VRP3V3A on TOP (solid shape): 207.46,24.9 208.73,24.9 209.04,24.59 209.62,24.59 209.62,22.2 209.37,21.95 204.03,21.95 203.4,21.31 203.4,20.3 203.2,20.09 201.04,20.09 200.83,20.3 200.83,24.92 201.19,25.28 207.08,25.28
VRP3V3A_PH on TOP (solid shape): 197.79,25.33 197.79,20.2 197.63,20.04 195.81,20.04 195.75,20.09 195.75,22.69 193.83,24.61 193.83,24.96 195.06,24.96 195.6,25.51 197.61,25.51
VRP3V3A_VIN on TOP (solid shape): 190.12,27.56 191.21,27.56 192.27,26.5 192.27,25.86 192.45,25.68 193.54,25.68 193.62,25.61 193.62,25.12 193.14,25.12 192.76,24.74 188.02,24.74 187.36,24.08 184.65,24.08 184.6,24.13 184.6,27.38 184.78,27.56 185.98,27.56 186.56,28.15 189.53,28.15
VRP5V0 on BOTTOM (solid shape): 55.37,82.35 55.37,78.69 54.59,77.92 54.59,76.72 54.38,76.51 53.31,76.51 53.06,76.76 51.78,76.76 51.78,76.77 50.69,76.77 50.69,76.52 50.67,76.51 49.15,76.51 48.87,76.79 48.87,80.49 54.2,80.49 54.2,81.2 53.56,81.2 53.56,80.49 48.87,80.49 48.87,82.58 49.02,82.73 54.99,82.73
VRP5V0_PH on BOTTOM (solid shape): 59.18,83.19 59.18,82.55 60.09,81.64 60.09,80.9 60.09,80.86 60.1,80.79 60.11,80.72 60.14,80.65 60.17,80.58 60.21,80.52 60.26,80.46 60.32,80.41 60.38,80.37 60.44,80.33 60.51,80.3 60.58,80.28 60.58,79.73 59.71,79.73 59.64,79.66 59.17,79.66 58.86,79.35 57.07,79.35 56.87,79.56 56.87,80.5 59.34,80.5 59.34,81.21 58.7,81.21 58.7,80.5 56.87,80.5 56.87,82.71 57.55,83.39 58.98,83.39
VRP5V0_VIN on BOTTOM (solid shape): 64.89,84.28 65.73,84.28 65.86,84.15 65.87,84.03 65.91,83.92 65.91,83.06 64.67,81.82 63.8,81.82 63.54,81.55 62.98,81.45 62.72,80.94 62.72,80.89 62.62,80.8 62.53,80.67 62.46,80.52 61.06,80.52 61.03,80.55 61.03,81.97 61.44,82.38 61.44,83.82 61.67,84.05 62.73,84.05 63.6,84.92 64.26,84.92
VRP5V0A on TOP (solid shape): 260.21,24.48 260.22,24.4 260.25,24.34 260.25,23.42 259.76,22.94 259.76,21.42 259.49,21.42 259.49,21.16 255.65,21.16 255.29,20.81 255.29,20.17 255.22,20.09 253.23,20.09 253.08,20.25 253.08,24.67 253.34,24.92 259.76,24.92
VRP5V0A_PH on TOP (solid shape): 250.29,25.84 250.29,20.27 250.11,20.09 247.65,20.09 247.49,20.25 247.49,23.98 246.91,24.57 246,24.57 246,25.28 246.96,26.24 249.88,26.24
VRP5V0A_VIN on TOP (solid shape): 243,29.54 243,27.92 243.3,27.61 245.41,27.61 245.44,27.59 245.44,25.4 245.36,25.33 243.96,25.33 243.86,25.43 243.86,25.86 243.66,26.06 243.23,26.06 243.02,25.86 243.02,25.51 242.9,25.38 241.98,25.38 241.68,25.07 240.38,25.07 239.87,24.57 239.87,23.6 239.8,23.52 237.13,23.52 237.08,23.57 237.08,25.2 237.51,25.63 237.51,25.78 238.3,26.57 238.3,28.35 237.61,29.04 237.61,29.75 237.69,29.82 242.72,29.82
VRPCHG_PH on BOTTOM (solid shape): 48.1,31.27 48.1,30.53 48.36,30.28 48.56,30.28 49.02,30.28 49.17,30.13 49.17,26.62 49.12,26.57 47.75,26.57 47.44,26.27 47.44,25.05 47.29,24.9 44.35,24.9 44.22,25.02 44.22,28.71 44.37,28.86 45.62,28.86 45.89,29.14 45.89,31.25 45.99,31.34 46.12,31.34 46.15,31.35 48.03,31.35
VRPGPU_SW1 on BOTTOM: 160.73,58.19 160.73,55.63 163.34,55.63 163.34,57.31 163.78,57.74 164.61,57.74 165.02,58.14 165.02,59.16 165.48,59.62 165.48,63.07 164.79,63.76 160.19,63.76 159.61,63.17 159.61,59.97 160.17,59.41 160.17,58.75
VRPGPU_SW2 on BOTTOM: 170.66,58.19 170.66,55.63 173.28,55.63 173.28,57.31 173.71,57.74 174.55,57.74 174.95,58.14 174.95,59.16 175.41,59.62 175.41,63.07 174.72,63.76 170.13,63.76 169.54,63.17 169.54,59.97 170.1,59.41 170.1,58.75
VRPGPU_SW3 on BOTTOM: 180.67,58.19 180.67,55.63 183.28,55.63 183.28,57.31 183.71,57.74 184.55,57.74 184.96,58.14 184.96,59.16 185.42,59.62 185.42,63.07 184.73,63.76 180.13,63.76 179.55,63.17 179.55,59.97 180.11,59.41 180.11,58.75
VRPGPU_SW4 on BOTTOM: 190.67,58.25 190.67,55.68 193.29,55.68 193.29,57.36 193.72,57.79 194.56,57.79 194.97,58.19 194.97,59.21 195.42,59.67 195.42,63.12 194.74,63.81 190.14,63.81 189.56,63.22 189.56,60.02 190.12,59.46 190.12,58.8
VRPGPU_SW5 on BOTTOM: 200.68,58.22 200.68,55.65 203.3,55.65 203.3,57.33 203.73,57.76 204.57,57.76 204.97,58.17 204.97,59.19 205.43,59.64 205.43,63.1 204.75,63.78 200.15,63.78 199.56,63.2 199.56,60 200.12,59.44 200.12,58.78
VRPGPU_SW6 on BOTTOM: 210.69,58.25 210.69,55.68 213.31,55.68 213.31,57.36 213.74,57.79 214.58,57.79 214.98,58.19 214.98,59.21 215.44,59.67 215.44,63.12 214.75,63.81 210.16,63.81 209.57,63.22 209.57,60.02 210.13,59.46 210.13,58.8
VRPGT_PH1 on BOTTOM: 68.53,128.73 71.35,128.73 72.06,129.44 72.06,132.52 79,139.46 77.06,141.41 77.01,141.41 68.22,132.62 68.22,129.04
VRPSA_PH1 on BOTTOM: 139.7,173.74 141.83,173.74 142.01,173.56 142.01,166.48 141.58,166.04 137.89,166.04 137.89,168.81 138.1,169.02 139.16,169.02 139.6,169.45 139.6,173.64
VRPVBAT_DGPU on BOTTOM (solid shape): 220.11,61.12 220.11,58.78 219.88,58.55 216.84,58.55 216.63,58.75 216.63,61.04 216.84,61.24 219.99,61.24
VRPVBAT_DGPU on TOP: 161.16,43.11 161.16,47.6 206.14,47.6 207.74,49.2 212.47,49.2 213.48,50.22 216.28,50.22 216.99,50.93 216.99,60.61 217.19,60.81 220.93,60.81 221.13,60.61 221.13,49.56 214.47,42.9 178.63,42.9 175.79,40.06 168.73,40.06 165.88,42.9 161.36,42.9 ; 1 cut-out
VRPVBAT_DGPU on BOTTOM: 170.23,43.03 161.31,43.03 161.19,43.16 161.19,45.37 161.31,45.49 170.2,45.49 170.38,45.32 170.38,43.18
VRPVBAT_NVVDD on TOP (solid shape): 181.1,52.94 181.1,50.27 180.97,50.14 178.13,50.14 178,50.27 178,52.94 178.13,53.06 178.96,53.06 178.98,53.06 180.97,53.06
VRPVBAT_NVVDD on TOP (solid shape): 190.93,52.99 190.93,50.32 190.8,50.19 187.96,50.19 187.93,50.22 187.93,53.09 187.96,53.11 188.97,53.11 188.99,53.11 190.8,53.11
VRPVBAT_NVVDD on TOP (solid shape): 210.99,52.99 210.99,50.32 210.87,50.19 208.02,50.19 207.9,50.32 207.9,52.99 208.02,53.11 209.03,53.11 209.05,53.11 210.87,53.11
VRPVBAT_NVVDD on TOP (solid shape): 171.19,52.94 171.19,50.27 171.07,50.14 168.22,50.14 168.09,50.27 168.09,52.94 168.19,53.04 168.98,53.04 169.06,53.04 169.16,53.06 171.07,53.06
VRPVBAT_NVVDD on TOP (solid shape): 201.01,52.99 201.01,50.32 200.89,50.19 198.04,50.19 197.91,50.32 197.91,52.93 198.08,53.09 199.01,53.09 199.09,53.1 199.19,53.11 200.89,53.11
VRPVBAT_NVVDD on TOP (solid shape): 161.41,52.96 161.41,51.03 161.21,50.83 158.85,50.83 158.31,51.36 158.31,52.96 158.39,53.04 159.08,53.04 159.2,53.05 159.33,53.09 161.29,53.09
VRPVBAT_NVVDD on L3 (solid shape): 161.29,53.06 161.29,50.6 161.16,50.47 158.37,50.47 158.19,50.65 158.19,53.06 158.31,53.19 161.16,53.19
VRPVBAT_NVVDD on L3 (solid shape): 190.88,53.22 190.88,50.6 190.75,50.47 187.96,50.47 187.78,50.65 187.78,53.22 187.91,53.34 190.75,53.34
VRPVBAT_NVVDD on L3 (solid shape): 201.01,53.19 201.01,50.7 200.78,50.47 198.12,50.47 197.91,50.68 197.91,53.19 198.04,53.32 200.89,53.32
VRPVBAT_NVVDD on L3 (solid shape): 210.89,53.14 210.89,50.55 210.82,50.47 207.9,50.47 207.79,50.57 207.79,53.14 207.92,53.27 210.77,53.27
VRPVBAT_NVVDD on L3 (solid shape): 171.01,53.19 171.01,50.68 170.81,50.47 168.14,50.47 167.92,50.7 167.92,53.19 168.04,53.32 170.89,53.32
VRPVBAT_NVVDD on L3 (solid shape): 180.84,53.22 180.84,50.6 180.72,50.47 177.92,50.47 177.75,50.65 177.75,53.22 177.87,53.34 180.72,53.34
VRPVBAT_NVVDD on BOTTOM: 209.04,59.06 209.04,58.25 209.65,57.64 209.98,57.64 210.05,57.56 210.05,56.8 210.08,56.77 210.41,56.77 210.44,56.8 210.44,58.55 209.9,59.08 209.06,59.08
VRPVBAT_NVVDD on BOTTOM: outline of 91 points within 156.94,45.77 217.55,59.06
VRPVBAT_NVVDD on BOTTOM: 168.98,59.03 168.98,58.22 169.59,57.61 169.92,57.61 170,57.53 170,56.77 170.02,56.75 170.35,56.75 170.38,56.77 170.38,58.53 169.85,59.06 169.01,59.06
VRPVBAT_NVVDD on BOTTOM: 188.97,59.06 188.97,58.25 189.58,57.64 189.91,57.64 189.99,57.56 189.99,56.8 190.01,56.77 190.34,56.77 190.37,56.8 190.37,58.55 189.84,59.08 189,59.08
VRPVBAT_NVVDD on BOTTOM: 180.03,56.77 180.03,57.51 179.9,57.64 179.57,57.64 178.97,58.25 178.97,59.06 178.99,59.08 179.83,59.08 180.36,58.55 180.36,56.8 180.34,56.77
VRPVBAT_NVVDD on BOTTOM: 199.01,59.06 199.01,58.25 199.62,57.64 199.95,57.64 200.02,57.56 200.02,56.8 200.05,56.77 200.38,56.77 200.4,56.8 200.4,58.55 199.87,59.08 199.03,59.08
VRPVCCIO on BOTTOM: 73.96,111.66 75.13,111.66 75.43,111.36 76.48,111.36 77.06,110.77 79.17,110.77 79.42,110.52 79.42,104.09 79.12,103.79 76.15,103.79 74.93,105.01 74.93,107.62 73.81,108.74 73.81,111.51
VRPVCCIO_PH on BOTTOM (solid shape): 73.15,107.39 73.15,103.66 72.82,103.33 71.17,103.33 70.72,103.78 70.72,103.79 70.71,103.79 70.38,104.12 70.38,105.42 71.28,105.42 71.28,106.13 70.65,106.13 70.65,105.42 70.38,105.42 70.38,105.67 68.4,105.67 68.4,106.02 70.35,106.02 70.35,107.39 70.61,107.65 72.89,107.65
VRPVCCIO_VIN on BOTTOM (solid shape): 67.94,105.52 68.53,105.52 68.53,105.16 67.51,105.16 67.21,104.85 67.21,103.53 67.18,103.51 65.68,103.51 65.48,103.71 65.07,103.71 65,103.79 65,104.02 64.49,104.52 64.49,105.44 64.64,105.59 66.82,105.59 66.95,105.72 67.74,105.72
VRPVDDQ on BOTTOM: 68.96,75.11 75.56,75.11 75.69,74.98 75.69,72.7 75.94,72.44 75.94,71.43 68.96,71.43 68.7,71.68 68.7,74.86
VRPVDDQ_PH on BOTTOM (solid shape): 71.99,81.81 71.99,81.78 72,81.72 72,81.69 72,81.46 72,81.43 71.99,81.35 71.99,81.28 72,81.2 72.02,81.13 72.04,81.06 72.07,81 72.11,80.93 72.13,80.9 72.13,80.57 72.34,80.37 72.66,80.37 72.91,80.11 73.2,80.11 73.44,79.88 73.44,79.84 73.46,79.78 73.49,79.72 73.52,79.66 73.56,79.6 73.58,79.57 73.58,76.03 73.33,75.77 67.05,75.77 66.9,75.92 66.9,77.09 67.21,77.4 67.76,77.4 68.14,77.78 68.14,78.54 68.91,79.31 71.78,79.31 71.78,79.94 71.07,79.94 71.07,79.31 68.91,79.31 69.85,80.24 70.76,80.24 71.04,80.52 71.04,81.92 71.07,81.94 71.85,81.94
VRPVDDQ_VIN on BOTTOM (solid shape): 70.96,88.55 70.96,83.21 70.86,83.11 70.58,83.11 70.43,83.26 70.43,84.03 70.33,84.12 70.33,84.13 68.86,85.6 68.42,85.6 68.25,85.78 68.25,86.67 68.88,87.3 68.88,88.57 69.01,88.7 70.81,88.7
VRPVTT on BOTTOM (solid shape): 75.94,83.62 75.94,83.49 75.43,82.99 75.43,82.48 75.31,82.35 75.01,82.35 74.92,82.55 74.77,82.71 73.89,82.71 73.83,82.76 73.83,83.47 73.86,83.49 74.8,83.49 75.05,83.75 75.82,83.75

Small or netless copper shapes (teardrops, artwork), in the pictures only: 3124 on TOP, 6403 on BOTTOM, 2543 on L3, 3584 on L5, 3870 on L8, 2857 on L10

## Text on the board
Ref Des/Silkscreen Bottom: COVINI-6050A3087801-TURBO-AX2(S2) | COVINI-6050A3087901-HALLSENSOR-AX2(S2)
User.Comments: CR_UNNAMED_1 | 7 | 4 | CR_UNNAMED_2
Ref Des/Silkscreen Top: COVINI-6050A3090101-USB-AX2(S2) | COVINI-6050A3087701-MB-AX2(S2)
User.30: 0.1uF_25V_2_DY | AMC_AZ5125_01H_SOD523_2P_DY | AMC_AZ5125_01H_SOD523_2P | 0.22uF_6.3V_2 | 0.047uF_25V_2 | 0.022uF_16V_2 | 0.033uF_16V_2 | short_0402_15 | 10uF_6.3V_2_DY | 1uF_6.3V_2_DY | 0.22uF_6.3V_1 | 1uF_6.3V_1 | 60.4K_1%_2_DY | short_0402_15_nsp | 0.1uF_16V_2_DY | CSC0201_DY | 4.7UF_6.3V_2_DY | BLM15PD600SN1D | 1000PF_50V_2_DY | AMAZING_AZ1045_04F_R7G_10P | 0.1uF_6.3V_1 | AMC_AZC099_04S_R7G_SOT23_6P | 220pF_50V_2_DY | 10pF_50V_2_DY | AMC_AZ2015_01H_SOD523_2P_DY | FBMA_11_160808_300A25T | TI_TPS22965DSGR_SON_8P | SILERGY_SY8088AAC_SOT23_5P | ANPEC_APL3526QBI_TRG_TDFN_8P | 18pF_50V_2_DY | SFI_SFI0402ML120C_LF_SMD_2P_DY | 20K_1%_2_DY | CSC0402_DY | 0.1uF_16V_2 | 1000PF_50V_2 | 0.1uF_25V_2 | short_0402_5 | 22pF_50V_2 | 10K_5%_2_DY | 100pF_50V_2 | POWERPAD1x1m | TP26 | 3300pF_50V_2 | 4.64K_1%_2 | 93.1K_1%_2 | TP24 | 1K_5%_2_DY | 2200pF_50V_2 | 6800pF_25V_2 | 10uF_6.3V_2 | 47pF_50V_2 | 1uF_6.3V_2 | 33.2K_1%_2 | 0.01uF_50V_2 | 4.99K_1%_2 | 2.2UF_6.3V_2 | 61.9K_1%_2 | RSC_0402_NTC | 100K_1%_2_DY | 4.7uF_6.3V_2 | 3.9pF_50V_2 | 220pF_50V_2 | MST_MH255ESP_PSOT23_3P | 20.5K_1%_2 | SILERGY_SY8284RAC_QFN_20P | 330pF_50V_2 | 2M_5%_2_DY | ANPEC_APL3523A_TDFN_14P | SILERGY_SY8288CRAC_QFN_21P | 2.2K_5%_2_DY | 10K_1%_2_DY | DIPTRONICS_T1A2QR_4P | 100K_5%_2_DY | 12pF_50V_2 | HCB1608KF_221T20 | 1uF_16V_2_DY | 10pF_50V_2 | 22K_1%_2_DY | 4.7K_5%_2_DY | MCF12102G900-T | 1K_1%_2_DY | 11K_1%_2_DY | PARADE_PS8713BTQFN24GTR2_A3_TQFN_24P | 10uF_6.3V_3_DY | 54.9K_1%_2 | 1200pF_50V_2 | 470pF_50V_2 | 26.7K_1%_2 | 6.98K_1%_2 | 66.5K_1%_2 | 4.7UF_6.3V_2 | 200K_5%_2_DY | 75K_1%_2_DY | 71.5K_1%_2 | PANJIT_2N7002KW_3P | 19.6K_1%_2 | 30.1K_1%_2 | TEXAS_TPS2546RTER_QFN_16P | 1M_5%_2_DY | 2.37K_1%_2 | 0.22UF_25V_2 | 0.33UF_25V_2 | GMT_G518B1TP1U_TSOT23_6P | EVL_12_22UYOSUBC_S530_A4_TR8_3P | 4.7K_5%_2 | 22K_5%_2 | 4.7uF_6.3V_3 | short_0603_25 | 100K_5%_2 | 200K_5%_2 | 10uF_6.3V_3 | 61.9_1%_2 | 10K_5%_2 | 100_5%_2 | 49.9_1%_2 | 270pF_50V | RSC_0402 | 24.9_1%_2 | 16K_1%_2 | 499_1%_2 | 7.5K_1%_2 | 14K_1%_2 | 12.1_1%_2 | 22uF_6.3V_3 | 2.2K_5%_2 | 56.2_1%_2 | 47UF_6.3V_5_DY | 100_1%_2 | 220_1%_2 | 100K_1%_2 | 10K_1%_2 | POWERPAD_2_0610 | 22UF_6.3V_3 | 121_1%_2 | POWERPAD_4_0610 | TAI_TECH_HPC4018B_2R2M | 60.4_1%_2 | 20K_5%_2 | 200_1%_2 | L2N7002WT1G | ITE_IT66317FN_BW_0006_R_QFN_48P | 22K_1%_2 | 0_5%_2_DY | 220K_5%_2 | 47K_5%_2 | 4.7uF_10V_3 | 4.7uF_25V_3 | 75K_1%_2 | 165K_1%_2 | 5.1K_1%_2 | 13K_1%_2 | 45.3_1%_2 | 1uF_10V_2 | 220_5%_2 | 240_1%_2 | 402_1%_2 | 150_1%_2 | 40.2_1%_2 | MPS_NB680AGD_Z_QFN_12P | WINB_W25Q128JVSIQ_SOIC_8P | 300_5%_2 | 33K_1%_2 | WCM_2012SHS_850T | AMAZING_AZ1065_06F_10P | 12_215_BHC_ZLMRY_3C | 3K_1%_2 | 10_1%_2 | 1K_1%_2 | STANDOFF_3.2_6.0 | 2_1%_2 | CSC0402 | 51_5%_2 | 1K_5%_2 | 20_5%_2 | 2K_1%_2 | 47UF_4V_3 | 47UF_6.3V_5 | 0_5%_2 | 10uF_10V_5 | 22uF_4V_3 | SYNNEX_SM3303PSQG | 10uF_4V_3 | RSC_0603 | 30_5%_2 | 33_5%_2 | 22_5%_2 | 1M_5%_2 | LMBT3904LT1G | RIVET_E2500_RIV1_RL_QFN_40P | EM6K1GT2R | 0_5%_3_DY | 22uF_6.3V_5 | 22_1%_2 | 10UF_25V_5 | 75_5%_2 | 75_1%_2 | ON_NCP81215MNTXG_QFN_52P | 2_5%_2 | 1M_1%_2 | MPS_MP2886AGU_Z_QFN_40P | 4.7uF_25V_5 | 3.3_5%_3 | 150_5%_3 | 2N7002KDW | 22UF_6.3V_5 | 15_5%_2 | REA_ALC255_CG_MQFN_48P | 10_5%_3 | CYNTEC_PCMB062D_1R5MS | CYNTEC_PCMB053T_2R2MS | CSC0603 | ACES_50696_0100M_001_10P | FIX_MASK | 0_5%_5_DY | 4.7uH_20% | 75_5%_3 | 2.2_5%_5 | PERICOM_PI3DPX1203BZHEX_TQFN_42P | 0_5%_3 | SCREW390_850_700_1P | SCREW280_850_700_1P | 0.005_1%_6 | 25MHz_10pF | SCREW280_900_550_NP_1P | CSC0805 | ACES_50505_00401_001_4P | SCREW280_700_1P | SCREW280_900_700_1P | SCREW420_700_1P | PJA138K | SCREW500_900_NP_1P | PM513BA | SCREW390_700_1P | CSC_AX1.6 | PM514BA | ACES_91960_0084L_8P | SCREW500_800_NP_1P | SCREW390_1160_850_1P | PCMC063T_2R2MN | 15uF_25V
User.31: 680pF_50V_2_DY | short_0402_15 | 100pF_50V_2_DY | RICHTEK_RT8097ALGE_TSOT23_6P | 0.22uF_6.3V_2 | PHILIPS_74LVC1G32_TSOT353_5P | LITEON_L30ESDXVC3_2_DSOT23_3P_DY | 0.22uF_6.3V_1 | ON_NCP81253MNTBG_DFN_8P | 1uF_6.3V_1 | 0.015uF_50V_2 | ANPEC_APL3537BHAI_TRG_WLCSP_6P | 60.4K_1%_2_DY | SFI_SFI0402ML120C_LF_SMD_2P_DY | 0.1uF_16V_2_DY | 47pF_50V_2_DY | 100K_5%_1 | 0.1uF_6.3V_1 | AMC_AZ5125_01H_SOD523_2P | BLM15PD600SN1D | 10pF_50V_2_DY | AMAZING_AZ5525_01F_R7G_DFN1006P2X_2P_DY | AMAZING_AZ1045_04F_R7G_10P | 0.047uF_16V_2 | CSC0201_DY | 0.022uF_16V_2 | short_0402_15_nsp | short_0402_5_nsp | RICHTEK_RT8068AZQW_WDFN_10P | 12pF_50V_2_DY | 220pF_50V_2_DY | BLM15AG121SN1D_500mA | MCF12102G900-T_DY | NXP_74LVC1G08GW_TSOT353_5P | 470pF_50V_2_DY | SFI_SFI0402ML120C_LF_SMD_2P | 1000PF_50V_2 | NUVO_NCT3521U_SOT23_5P | 0.1uF_16V_2 | 2.2UF_6.3V_2 | LITTELFUSE_0805L110ULYR | CSC0402_DY | 100K_5%_2_DY | 2.2K_5%_2_DY | 100K_5%_2 | 2200pF_50V_2 | TP24 | 1uF_6.3V_2 | SILERGY_SY8284CRAC_QFN_20P | 470pF_50V_2 | POWERPAD1x1m | short_0402_5 | TP26 | 0.1uF_25V_2 | 0.01uF_50V_2 | 2M_5%_2_DY | 0.22uF_16V_2 | 32.4K_1%_2 | ON_NCP81151MNTBG_DFN_8P | 1K_5%_2_DY | DIODE-BAT54-TAP-PHP_DY | 10K_5%_2_DY | 2.2uF_6.3V_2 | 100K_1%_NTC | PANJIT_2N7002KW_3P | DIODE-BAT54-TAP-PHP | 2.49K_1%_2 | NUVOTON_NCT7718W_MSOP_8P | 10pF_50V_2 | 4.7uF_6.3V_2 | 100K_1%_2_DY | 10K_1%_2_DY | 2.21K_1%_2 | ANPEC_APL3523A_TDFN_14P | 4.7UF_6.3V_2 | RICHTEK_RT8816A_QFN_20P | 60.4K_1%_2 | 7.87K_1%_2 | 25.5K_1%_2 | 15pF_50V_2 | 10K_5%_1 | 12pF_50V_2 | 18pF_50V_2 | 4.7K_5%_2_DY | 220pF_50V_2 | 100pF_50V_2 | 8.45K_1%_2 | GMT_G5250Q1T73U_SOT23_3P | MCF12102G900-T | SEM_SM24_SOT23_3P_DY | LS_Short_0504 | 49.9K_1%_2 | 10.2K_1%_2 | 10uF_6.3V_2 | 18.7K_1%_2 | 22pF_50V_2 | 37.4K_1%_2 | 24.9K_1%_2 | 40.2K_1%_2 | 0.1uF_25V_3_DY | 90.9K_1%_2 | 30K_1%_2_DY | SILERGY_SY8288RAC_QFN_20P | 4700pF_50V_2 | 100_5%_2_DY | 4.99K_1%_2 | PARADE_PS8713BTQFN24GTR2_A3_TQFN_24P | GMT_G524B1T11U_SOT23_5P | 0.33UF_25V_2 | 0.22UF_25V_2 | 120OHM_25%_6A | 100_5%_2 | 470K_5%_2 | L2N7002WT1G | BAT54C_30V_0_6A | AOS_AON7506_TRANSISTOR | 10K_5%_2 | 4.3K_5%_2 | RSC_0603_DY | 2.2uF_10V_3 | RSC_0402 | 10K_1%_2 | 60.4_1%_2 | POWERPAD_2_0610 | short_0603_25 | 4.7uF_6.3V_3 | MPS_NB685AGQ_Z_QFN_16P | 22uF_6.3V_3 | 100K_1%_2 | POWERPAD_4_0610 | 4.7uF_25V_3 | 1UF_25V_2 | PERICOM_PI3EQX12902A_TQFN_30P | 4.7K_5%_2 | 10uF_6.3V_3 | 33K_1%_2 | 2.2K_5%_2 | 0_5%_2_DY | 390_1%_2 | 75K_1%_2 | 649_1%_2 | ON_NCP45491XMNTWG_QFN_32P | 22UF_6.3V_3 | 287_1%_2 | WINBOND_W25Q80EWSNIG_SOP_8P | ACES_50224_0020N_001_2P | 47K_5%_2 | 200K_5%_2 | 133K_1%_2 | NUVOTON_NPCT750AAAYX_QFN_32P | 2.2UF_6.3V_3 | 432K_1%_2 | 27K_1%_2 | 4.7K_1%_2 | 200_5%_2 | 20K_5%_2 | 150_1%_2 | 10M_5%_2 | 200_1%_2 | 300_5%_2 | 120_5%_2 | 120K_1%_2 | 21K_1%_2 | WCM_2012SHS_850T | 220K_5%_2 | 1.8K_1%_2 | 5.1M_5%_2 | 0.1uF_25V_3 | 200K_1%_2 | 51K_1%_2 | BAT54C_30V_0_6A_DY | 1uF_10V_2 | 20K_1%_2 | BAT54_30V_0.2A_DY | MPS_NB681GD_Z_QFN_13P | 324K_1%_2 | TAI_TECH_HPC4018B_2R2M | 330_5%_2 | 130K_1%_2 | 4.3K_1%_2 | 110K_1%_2 | 470_5%_2 | 100_1%_2 | 24.9_1%_2 | 121_1%_2 | 681K_1%_2 | 365K_1%_2 | 243K_1%_2 | 68K_1%_2 | 220_5%_2 | 137K_1%_2 | 113_1%_2 | 2.2_5%_2 | 12.1_1%_2 | 22UF_6.3V_5_DY | 22uF_6.3V_5_DY | VIA_VP225_DFN_10P | 2N7002KDW | 0_5%_2 | 1M_5%_2 | 3M_5%_2 | 4.7K_5%_3 | 2.2_5%_3 | 22UF_6.3V_5 | CYNTEC_PCMB051H_3R3MS | 1K_1%_2 | 10_5%_2 | CSC0402 | RSC_0603 | 1K_5%_2 | 22uF_25V_5 | 1uF_25V_3 | 51_5%_2 | ON_NCP302045MNTWG_PQFN_33P | 47UF_6.3V_5 | CSC0603_DY | TC7SZ08FU | EM6K1GT2R | 33_1%_2 | 10uF_25V_5 | 10uF_4V_3 | 2K_5%_2 | 22uF_4V_3 | MPS_MP86941GQVT_Z_TQFN_21P | 43_5%_2 | 75_5%_2 | 10UF_25V_5 | 33_5%_2 | TXC_24MHZ_12PF | LMBT3904LT1G | 22_1%_2 | 22uF_6.3V_5 | 2K_1%_2 | SCREW280_900_550_NP_1P | 1N4148WS_DY | TI_BQ24780S_QFN_28P | 4.7uF_25V_5 | TC7SET08FU | 150_5%_3 | 127K_1% | 3.3_5%_3 | 0_5%_3_DY | 75_1%_2 | 30_5%_2 | 20_5%_2 | 10uF_10V_5 | 6 20_5% | ACES_50224_00401_001_4P | CSC0603 | CYN_PCMC063T_R68MN_4P | 47uF_4V_5 | 2.2_5%_5 | 10_5%_3 | 1000pF_2000V_6 | 100uF_6.3V_DY | TI_TLC59116_VQFN_32P | FIX_MASK | AOS_AONS32314 | ACES_50505_00401_001_4P | SCREW280_900_700_1P | CSC0805 | STANDOFF_3.2_6.0 | 330uF_2V_9mR_Pana_-35% | 0_5%_3 | 27MHz_10pF | MICRON_MT61K256M32JE_14_A_FBGA_180P | ACES_51540_01041_Q01_10P | 0.005_1%_6 | 10_5%_5 | MMBT4401 | NRS5020T1R0N | AOS_AON6992_8P | SCREW280_700_1P | AOS_AON6368 | ACES_50279_00401_Q01_4P | SCREW420_700_1P | SCREW390_850_700_1P | PM514BA | ALPHA_AON6994_8P | SCREW280_850_700_1P | PM513BA | ACES_51619_01401_001_14P | PJA138K | SCREW390_1160_850_1P | 32.768KHZ_12.5PF | SCREW500_900_NP_1P | SCREW390_700_1P | 100uF_6.3V | 0.01_1%_6 | 330uF_2.5V | MAGLAYERS_MMD_10CZ_R15MGX2I | PCME064T_R42MS1R557 | AOS_AON6996 | PCME063T-R24MS1R195 | SCREW500_800_NP_1P | SINGA_2SJ3095_123111F_7P | TCONN_22_M0081_1003_0_20P | SINGATRON_2UB3C02_101211F_24P | PCMC063T_3R3MN | BAV99 | 15uF_25V | ENTERY_6916K_Q08N_08L_8P | ITE_IT8987E_CX_LQFP_128P_HP | LOTES_APCI0062_P001A_NGFF_E_KEY_75P | ACES_50290_00801_001_8P | AON7752 | TRIO_EM_15BM66V03 | TRIO_EM_22BM66V04 | BOTH_NA0069RLF_SMD_24P | TCONN_18_35690_1A63_0_9P | SINGATRON_2RJ3104_038211F_8P | ACES_50458_00801_Q01_8P | ACES_51398_0407T_001_40P | 1.5A_24V | ENTERY_6905K_E28N_00R_28P | CSC_DX1.9 | ARGOSY_D4AR0_26010_1P52_260P | ARGOSY_D4AS0_26001_1P52_260P | 470uF_2V | ACES_51540_05001_001_50P | LOTUS_APCI0107_P001H_75P | INTEL_J43242_BGA_1440P | NVIDIA_N18E_G1_KD_QS_A1_BGA_2228P | INTEL_J44894_BGA_874P | TCONN_116B_2D023_20N_19P
User.33: D | C | B | A | 1 | 2 | 3 | 4 | 5 | 6
User.45: FIGURE | SIZE | 8.0 | 10.0 | 16.0 | 20.0 | 22.0 | 33.0 | 35.0 | 110.0 | 126.0 | 154.0 | 165.0 | 27.0 | 37.0 | 47.0 | 87.0 | 158.0 | 197.0 | 35.0x16.0 | 43.0x20.0 | 59.0x20.0 | 59.0x24.0 | 67.0x31.0 | 75.0x28.0 | 79.0x24.0 | 83.0x31.0 | 102.0x31.0 | 33.0x26.0 | 47.0x43.0 | 67.0x63.0 | DRILL CHART: TOP to BOTTOM | ALL UNITS ARE IN MILS | PLATED | NON-PLATED | QTY | 3225 | 5631 | 1 | 1336 | 10 | 19 | 27 | 8 | 11 | 3 | 5 | 7 | 2 | 6 | 4
